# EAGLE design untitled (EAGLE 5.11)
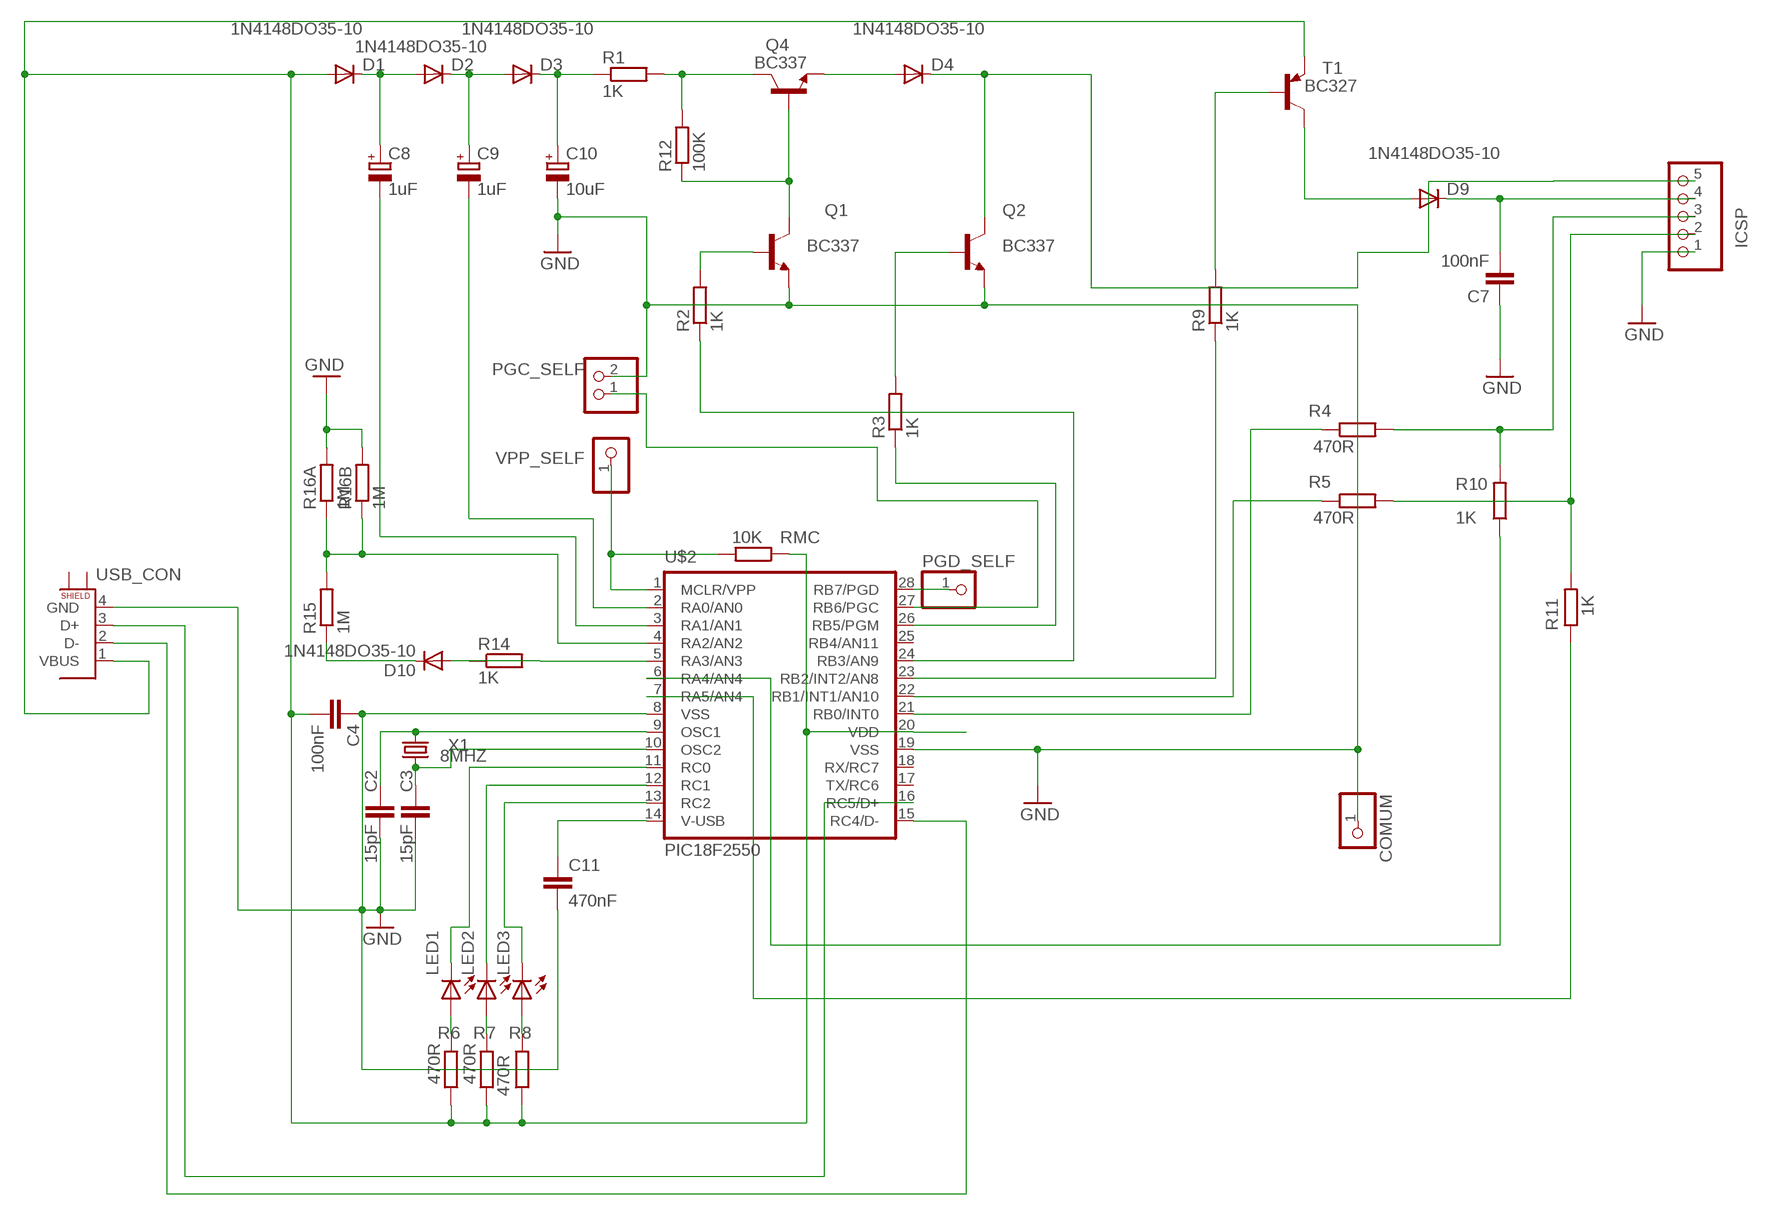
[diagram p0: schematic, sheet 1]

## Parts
C2  15pF  C-EU025-024X044  [C025-024X044]
C3  15pF  C-EU025-024X044  [C025-024X044]
C4  100nF  C-EU025-025X050  [C025-025X050]
C7  100nF  C-EU025-025X050  [C025-025X050]
C8  1uF  CPOL-EUE2-5  [E2-5]
C9  1uF  CPOL-EUE2-5  [E2-5]
C10  10uF  CPOL-EUE2-5  [E2-5]
C11  470nF  C-EU025-025X050  [C025-025X050]
COMUM  PINHD-1X1  [1X01]
D1  1N4148DO35-10  [DO35-10]
D2  1N4148DO35-10  [DO35-10]
D3  1N4148DO35-10  [DO35-10]
D4  1N4148DO35-10  [DO35-10]
D9  1N4148DO35-10  [DO35-10]
D10  1N4148DO35-10  [DO35-10]
ICSP  PINHD-1X5  [1X05]
LED1  LED3MM  [LED3MM]
LED2  LED3MM  [LED3MM]
LED3  LED3MM  [LED3MM]
PGC_SELF  PINHD-1X2  [1X02]
PGD_SELF  PINHD-1X1  [1X01]
Q1  BC337  [TO92]
Q2  BC337  [TO92]
Q4  BC337  [TO92]
R1  1K  R-EU_0207/10  [0207/10]
R2  1K  R-EU_0207/10  [0207/10]
R3  1K  R-EU_0207/10  [0207/10]
R4  470R  R-EU_0207/10  [0207/10]
R5  470R  R-EU_0207/10  [0207/10]
R6  470R  R-EU_0207/10  [0207/10]
R7  470R  R-EU_0207/10  [0207/10]
R8  470R  R-EU_0207/10  [0207/10]
R9  1K  R-EU_0207/10  [0207/10]
R10  1K  R-EU_0207/10  [0207/10]
R11  1K  R-EU_0207/10  [0207/10]
R12  100K  R-EU_0207/10  [0207/10]
R14  1K  R-EU_0207/10  [0207/10]
R15  1M  R-EU_0207/10  [0207/10]
R16A  1M  R-EU_0207/10  [0207/10]
R16B  1M  R-EU_0207/10  [0207/10]
RMC  10K  R-EU_0207/10  [0207/10]
T1  BC327  BC327-40-PNP-TO92-EBC  [TO92-EBC]
U$2  PIC18F2550  [DIL28-3]
USB_CON  USB-B  [PN61729]
VPP_SELF  PINHD-1X1  [1X01]
X1  8MHZ  CRYSTALHC49S  [HC49/S]

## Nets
GND: C2.2 C3.2 C4.1 C7.1 C10.- C11.2 COMUM.1 ICSP.1 PGC_SELF.2 Q1.1(E) Q2.1(E) R16A.2 R16B.2 U$2.8(VSS) U$2.19(VSS) USB_CON.4(GND)
N$1: C11.1 U$2.14(V-USB)
N$2: C8.+ D1.C D2.A
N$3: C9.+ D2.C D3.A
N$4: C10.+ D3.C R1.1
N$5: Q4.3(C) R1.2 R12.2
N$6: Q1.3(C) Q4.2(B) R12.1
N$7: Q1.2(B) R2.2
N$8: D4.A Q4.1(E)
N$9: Q2.2(B) R3.2
N$10: C2.1 U$2.9(OSC1) X1.2
N$11: C3.1 U$2.10(OSC2) X1.1
N$12: RMC.2 U$2.1(MCLR/VPP) VPP_SELF.1
N$13: LED1.A R6.2
N$14: LED2.A R7.2
N$15: LED3.A R8.2
N$16: D10.A R14.1
N$17: PGC_SELF.1 U$2.27(RB6/PGC)
N$18: R9.2 T1.B
N$19: C7.2 D9.C ICSP.4
N$20: ICSP.3 R4.2 R10.2
N$21: D9.A T1.C
N$22: ICSP.2 R5.2 R11.2
N$23: R15.2 R16A.1 R16B.1 U$2.4(RA2/AN2)
N$24: R3.1 U$2.26(RB5/PGM)
N$25: R14.2 U$2.5(RA3/AN3)
N$26: PGD_SELF.1 U$2.28(RB7/PGD)
PGC: R5.1 U$2.22(RB1/INT1/AN10)
PGD: R4.1 U$2.21(RB0/INT0)
PUMP1: C8.- U$2.3(RA1/AN1)
PUMP2: C9.- U$2.2(RA0/AN0)
RA4: R10.1 U$2.6(RA4/AN4)
RA5: R11.1 U$2.7(RA5/AN4)
RC0: LED1.K(C) U$2.11(RC0)
RC1: LED2.K(C) U$2.12(RC1)
RC2: LED3.K(C) U$2.13(RC2)
USBD+: U$2.16(RC5/D+) USB_CON.3(D+)
USBD-: U$2.15(RC4/D-) USB_CON.2(D-)
USBVDD: C4.2 D1.A R6.1 R7.1 R8.1 RMC.1 T1.E U$2.20(VDD) USB_CON.1(VBUS)
VDD_CTL: R9.1 U$2.23(RB2/INT2/AN8)
VPP: D4.C D10.C ICSP.5 Q2.3(C) R15.1
VPP_CTL: R2.1 U$2.24(RB3/AN9)
Unconnected: U$2.17(TX/RC6) U$2.18(RX/RC7) U$2.25(RB4/AN11) USB_CON.G1 USB_CON.G2

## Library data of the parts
C2-C4 C7 C11 = resistor:C-EU: CAPACITOR, European symbol
C8-C10 = resistor:CPOL-EU: POLARIZED CAPACITOR, European symbol
COMUM PGD_SELF VPP_SELF = pinhead:PINHD-1X1: PIN HEADER
D1-D4 D9 D10 = diode:1N4148: DIODE
ICSP = pinhead:PINHD-1X5: PIN HEADER
LED1-LED3 = led:LED: LED
PGC_SELF = pinhead:PINHD-1X2: PIN HEADER
Q1 Q2 Q4 = transistor:BC337: NPN TRANSISTOR
R1-R12 R14 R15 R16A R16B RMC = resistor:R-EU_: RESISTOR, European symbol
T1 = transistor:*-PNP-: PNP Transistror
U$2 = SparkFun:PIC18F2550
USB_CON = ads4:USB-B: USB Type-B Connector
X1 = crystal:CRYSTAL: CRYSTAL; OC_FARNELL: 1667008; OC_NEWARK: unknown

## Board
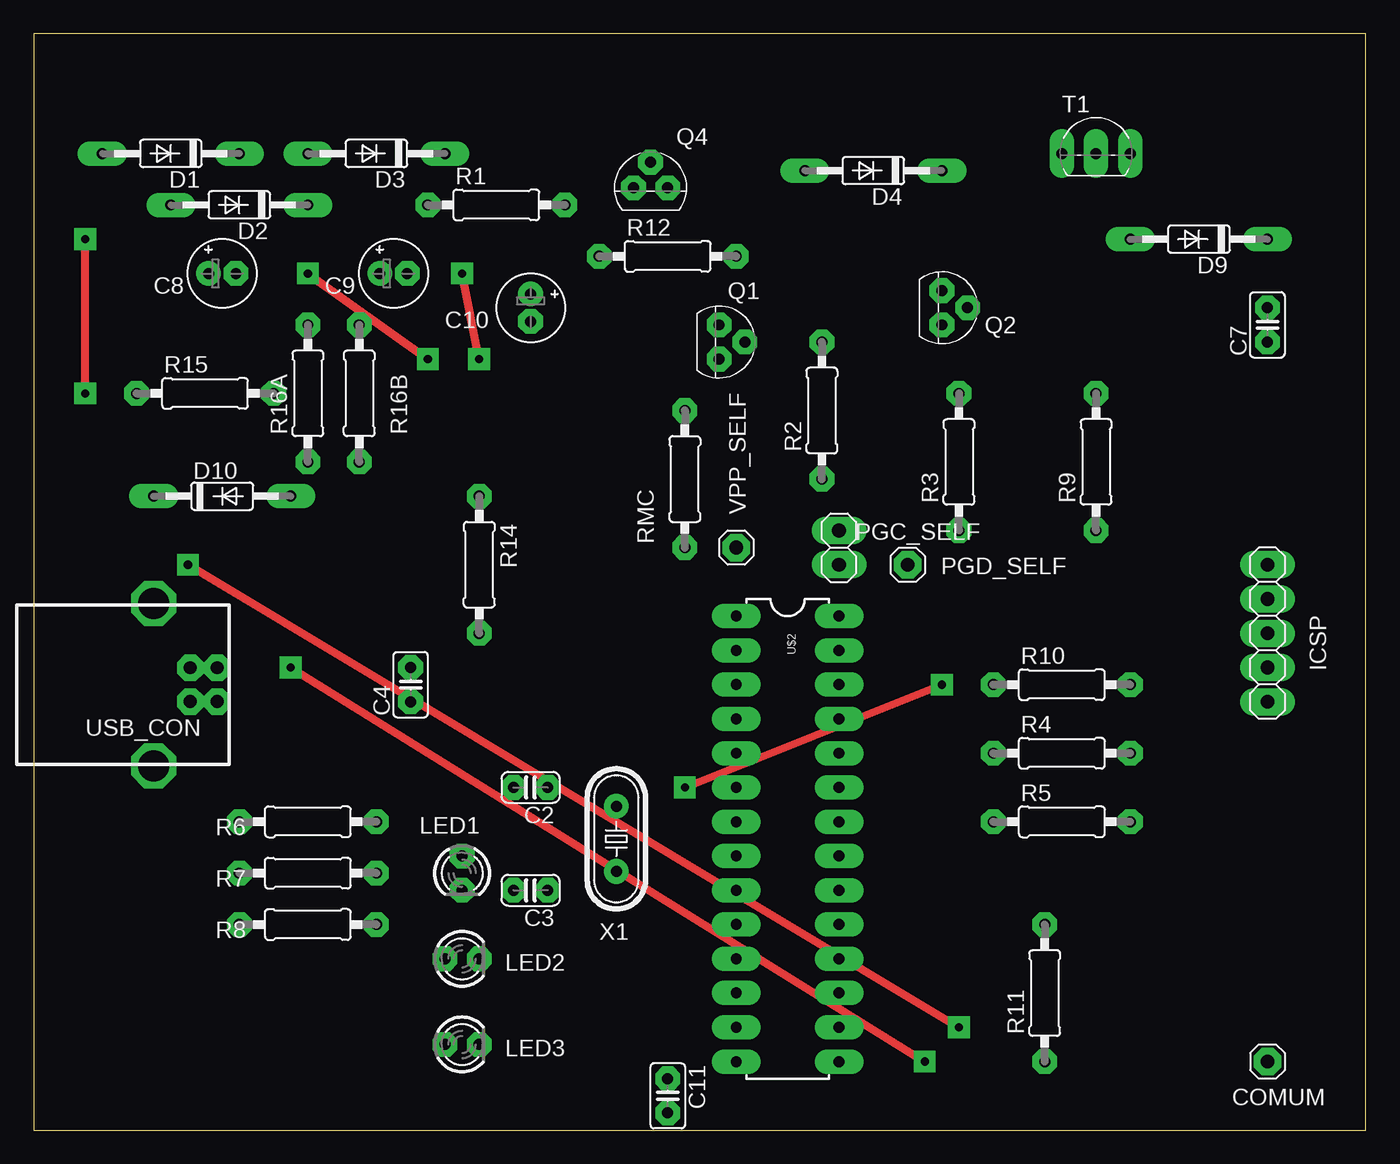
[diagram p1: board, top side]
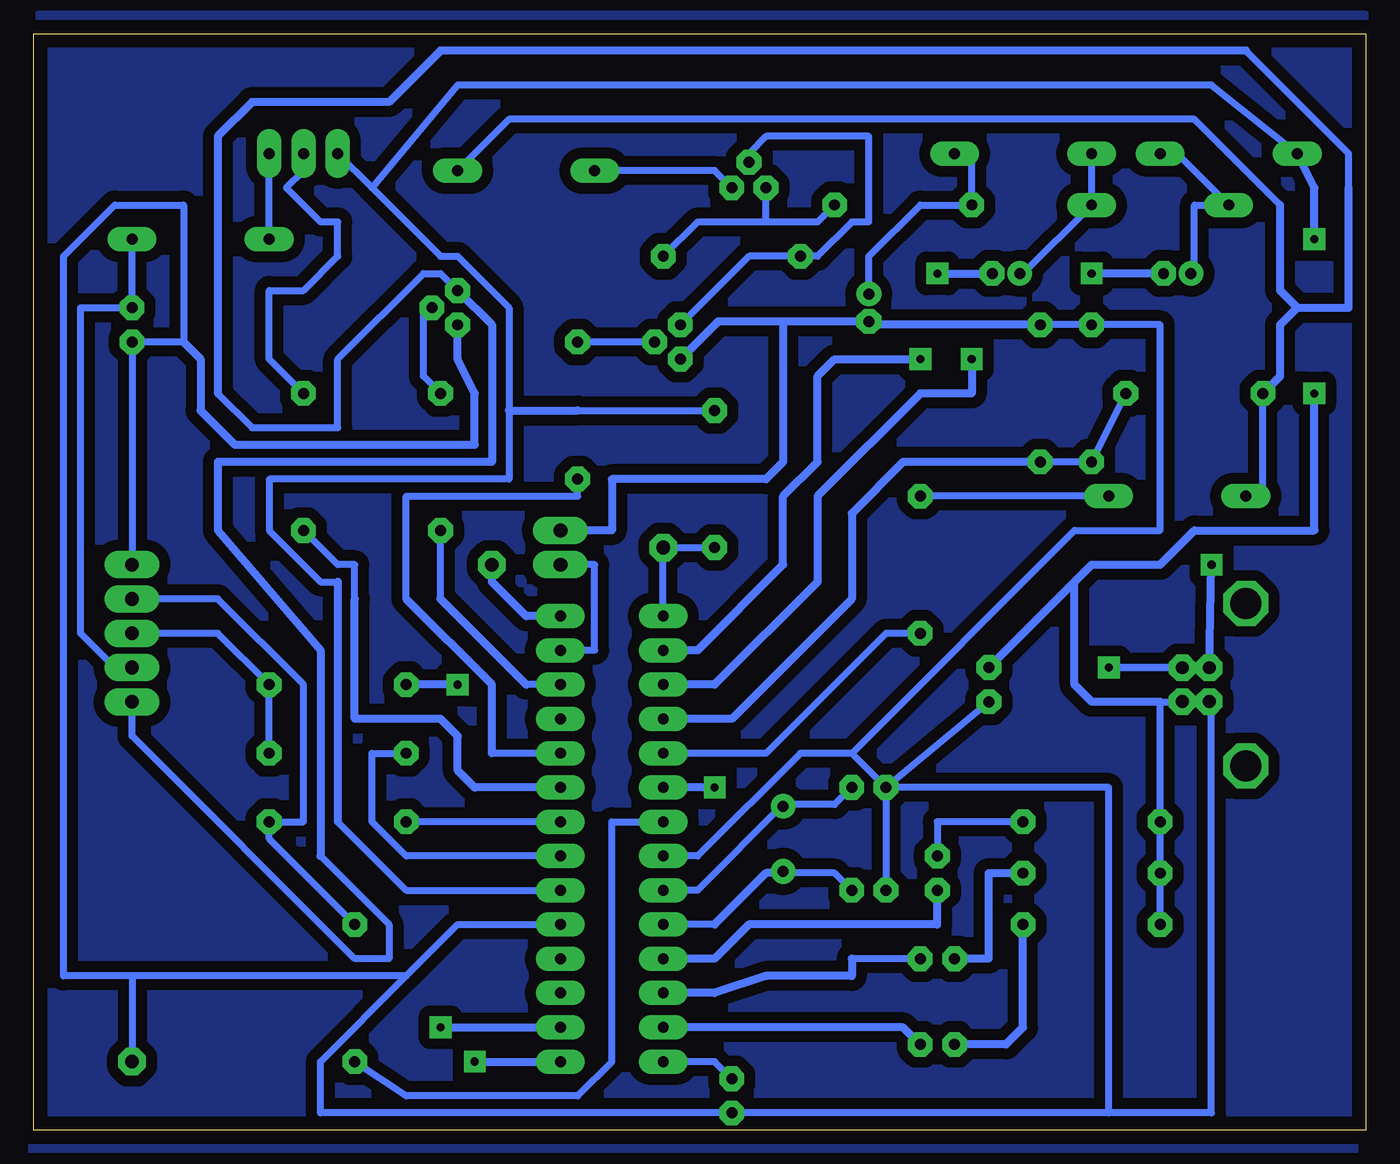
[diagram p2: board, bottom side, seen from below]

Size 98.73 x 81.27 mm. Coordinates in mm from the lower left corner, seen from the top.
Outline: 0,0 98.73,0 98.73,81.27 0,81.27 0,0
Copper layers (1*16): Top 0.035mm / dielectric 1.5mm / Bottom 0.035mm
Design rules "default *": minimum track width 20mil, minimum drill 24mil, track to track 20mil, track to pad 20mil, pad to pad 20mil, via to via 20mil, smd to smd 8mil, copper to edge 40mil, drill to drill 8mil, minimum pad ring 20mil, minimum via ring 20mil, stop-mask expansion 4mil, vias tented up to drill 0mil, thermal gap 10mil

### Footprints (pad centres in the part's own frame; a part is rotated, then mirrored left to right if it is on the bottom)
C025-024X044 = drill 0.813 octagon: 1 -1.27,0; 2 1.27,0
C025-025X050 = drill 0.813 octagon: 1 -1.27,0; 2 1.27,0
E2-5 = drill 0.813 pad 1.27 round: + -1.016,0 | drill 0.813 pad 1.27 octagon: - 1.016,0
1X01 = drill 1.016 octagon: 1 0,0
DO35-10 = drill 0.813 long: A 5.08,0; C -5.08,0
1X05 = drill 1.016 long: 1 -5.08,0; 2 -2.54,0; 3 0,0; 4 2.54,0; 5 5.08,0
LED3MM = drill 0.813 octagon: A -1.27,0; K 1.27,0
1X02 = drill 1.016 long: 1 -1.27,0; 2 1.27,0
TO92 = drill 0.813 octagon: 1 1.27,0; 2 0,1.905; 3 -1.27,0
0207/10 = drill 0.813 octagon: 1 -5.08,0; 2 5.08,0
TO92-EBC = drill 0.813 long: B 0,-1.27; C 2.54,-1.27; E -2.54,-1.27
DIL28-3 = drill 0.813 long: 1 -16.51,-3.81; 2 -13.97,-3.81; 3 -11.43,-3.81; 4 -8.89,-3.81; 5 -6.35,-3.81; 6 -3.81,-3.81; 7 -1.27,-3.81; 8 1.27,-3.81; 9 3.81,-3.81; 10 6.35,-3.81; 11 8.89,-3.81; 12 11.43,-3.81; 13 13.97,-3.81; 14 16.51,-3.81; 15 16.51,3.81; 16 13.97,3.81; 17 11.43,3.81; 18 8.89,3.81; 19 6.35,3.81; 20 3.81,3.81; 21 1.27,3.81; 22 -1.27,3.81; 23 -3.81,3.81; 24 -6.35,3.81; 25 -8.89,3.81; 26 -11.43,3.81; 27 -13.97,3.81; 28 -16.51,3.81
PN61729 = drill 0.95 octagon: 1 1.25,4.71; 2 -1.25,4.71; 3 -1.25,2.71; 4 1.25,2.71 | drill 2.3 octagon: G1 -6.02,0; G2 6.02,0
HC49/S = drill 0.813 round: 1 -2.413,0; 2 2.413,0

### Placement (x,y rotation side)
C2  36.83,25.4 180 top
C3  36.83,17.78 180 top
C4  27.94,33.02 90 top
C7  91.44,59.69 90 top
C8  13.97,63.5 0 top
C9  26.67,63.5 0 top
C10  36.83,60.96 270 top
C11  46.99,2.54 270 top
COMUM  91.44,5.08 0 top
D1  10.16,72.39 180 top
D2  15.24,68.58 180 top
D3  25.4,72.39 180 top
D4  62.23,71.12 180 top
D9  86.36,66.04 180 top
D10  13.97,46.99 0 top
ICSP  91.44,36.83 270 top
LED1  31.75,19.05 270 top
LED2  31.75,12.7 0 top
LED3  31.75,6.35 0 top
PGC_SELF  59.69,43.18 90 top
PGD_SELF  64.77,41.91 0 top
Q1  50.8,58.42 270 top
Q2  67.31,60.96 270 top
Q4  45.72,69.85 0 top
R1  34.29,68.58 0 top
R2  58.42,53.34 90 top
R3  68.58,49.53 90 top
R4  76.2,27.94 0 top
R5  76.2,22.86 0 top
R6  20.32,22.86 0 top
R7  20.32,19.05 0 top
R8  20.32,15.24 0 top
R9  78.74,49.53 90 top
R10  76.2,33.02 0 top
R11  74.93,10.16 90 top
R12  46.99,64.77 0 top
R14  33.02,41.91 270 top
R15  12.7,54.61 0 top
R16A  20.32,54.61 90 top
R16B  24.13,54.61 90 top
RMC  48.26,48.26 270 top
T1  78.74,73.66 0 top
U$2  55.88,21.59 270 top
USB_CON  8.89,33.02 270 top
VPP_SELF  52.07,43.18 0 top
X1  43.18,21.59 90 top

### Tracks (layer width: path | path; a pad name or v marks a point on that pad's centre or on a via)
GND
  Bottom 0.508: R16B.2 R16A.2 15.24,59.69 15.24,44.45 21.59,44.45 38.1,27.94 | C2.2 C4.1 | U$2.19 67.31,15.24 71.12,11.43 | 71.12,11.43 77.47,5.08 77.47,1.27 C11.2 19.05,1.27 | ICSP.1 C7.1 87.63,58.42 87.63,68.58 92.71,68.58 96.52,64.77 96.52,11.43 91.44,11.43 | 71.12,11.43 91.44,11.43 | U$2.8 49.53,20.32 41.91,27.94 38.1,27.94 | C2.2 38.1,27.94 | 19.05,1.27 11.43,1.27 11.43,31.75 USB_CON.4 | C2.2 C3.2 | C2.2 19.05,25.4 19.05,1.27 | 91.44,11.43 COMUM.1
  Bottom 0.61: Q2.1 67.31,57.15 66.04,54.61 66.04,50.8 83.82,50.8 86.36,53.34 86.36,57.15 87.63,58.42 | R16B.2 36.58,59.69 C10.- 43.18,59.94 | 43.18,59.94 48.01,59.94 Q1.1 | PGC_SELF.2 55.88,44.45 55.88,48.26 44.45,48.26 43.18,49.53 43.18,59.94
N$1
  Bottom 0.508: C11.1 48.26,5.08 U$2.14
N$2
  Bottom 0.508: D1.C 13.97,72.39 D2.A 12.7,68.58 12.7,63.5 C8.+
N$3
  Bottom 0.508: C9.+ 25.4,63.5 D2.C D3.A
N$4
  Bottom 0.508: D3.C 29.21,72.39 R1.1 33.02,68.58 36.83,64.77 C10.+
N$5
  Bottom 0.508: R1.2 40.64,67.31 44.45,67.31 | 44.45,67.31 49.53,67.31 R12.2 | 44.45,67.31 Q4.3
N$6
  Bottom 0.508: Q4.2 45.72,72.39 44.45,73.66 36.83,73.66 36.83,67.31 38.1,67.31 40.64,64.77 R12.1 45.72,64.77 Q1.3
N$7
  Bottom 0.508: Q1.2 R2.2
N$8
  Bottom 0.508: Q4.1 48.26,71.12 D4.A
N$9
  Bottom 0.508: R3.2 69.85,55.88 69.85,60.96 Q2.2
N$10
  Bottom 0.508: C2.1 39.37,24.13 43.18,24.13 | U$2.9 49.53,17.78 43.18,24.13 | 43.18,24.13 X1.2
N$11
  Bottom 0.508: C3.1 39.37,19.05 43.18,19.05 X1.1 | 48.26,15.24 U$2.10
  Bottom 0.61: 48.26,15.24 44.45,19.05 43.31,19.05 X1.1
N$12
  Bottom 0.508: U$2.1 VPP_SELF.1 RMC.2
N$13
  Bottom 0.508: LED1.A 31.75,22.86 R6.2
N$14
  Bottom 0.61: R7.2 27.94,19.05 27.94,12.7 LED2.A
N$15
  Bottom 0.61: LED3.A 26.67,6.35 25.4,7.62 R8.2
N$16
  Bottom 0.508: D10.A R14.1
N$17
  Bottom 0.508: U$2.27 57.15,35.56 57.15,41.91 PGC_SELF.1
N$18
  Bottom 0.508: R9.2 81.28,57.15 81.28,62.23 78.74,62.23 76.2,64.77 76.2,67.31 77.47,67.31 80.01,69.85 78.74,71.12 T1.B
N$19
  Bottom 0.508: D9.C C7.2 95.25,60.96 95.25,36.83 92.71,34.29 ICSP.4
N$20
  Bottom 0.508: R4.2 R10.2 85.09,36.83 ICSP.3
N$21
  Bottom 0.508: D9.A T1.C
N$22
  Bottom 0.508: R11.2 81.28,21.59 R5.2 78.74,22.86 78.74,33.02 85.09,39.37 ICSP.2
N$23
  Bottom 0.508: R15.2 R16A.1 R16B.1
  Bottom 0.61: R16B.1 34.29,49.53 38.1,45.72 38.1,39.37 46.99,30.48 U$2.4
N$24
  Bottom 0.508: U$2.26 62.23,33.02 | 68.58,39.37 R3.1
  Bottom 0.61: 62.23,33.02 68.58,39.37
N$25
  Bottom 0.508: U$2.5 44.45,27.94 35.56,36.83 R14.2
N$26
  Bottom 0.61: U$2.28 62.23,38.1 64.77,40.64 PGD_SELF.1
N$27
  pour Bottom (isolate 0.813): 0,0 0,82.55 98.42,82.55 99.06,81.92 99.06,-1.27 0.64,-1.27 0,-0.64
PGC
  Bottom 0.508: U$2.22 R5.1
PGD
  Bottom 0.508: U$2.21 71.12,20.32 73.66,22.86 73.66,27.94 R4.1
PUMP1  (via drill 0.6)
  Top 0.61: v20.32,63.5 v29.21,57.15
  Bottom 0.61: C8.- v20.32,63.5 | U$2.3 48.26,33.02 40.64,40.64 40.64,46.99 33.02,54.61 29.21,54.61 v29.21,57.15
PUMP2  (via drill 0.6)
  Top 0.61: v33.02,57.15 v31.75,63.5
  Bottom 0.61: v31.75,63.5 C9.- | v33.02,57.15 39.37,57.15 40.64,55.88 40.64,49.53 43.18,46.99 43.18,41.91 49.53,35.56 U$2.2
RA4  (via drill 0.6)
  Top 0.61: v48.26,25.4 v67.31,33.02
  Bottom 0.61: v67.31,33.02 R10.1 | v48.26,25.4 U$2.6
RA5
  Bottom 0.508: R11.1 71.12,2.54 58.42,2.54 55.88,5.08 55.88,22.86 U$2.7
RC0
  Bottom 0.61: U$2.11 48.26,12.7 45.72,15.24 31.75,15.24 LED1.K
RC1
  Bottom 0.508: LED2.K 38.1,12.7
  Bottom 0.61: 38.1,12.7 38.1,11.43 44.45,11.43 48.26,10.16 U$2.12
RC2
  Bottom 0.61: U$2.13 34.29,7.62 LED3.K
USBD+  (via drill 0.6)
  Top 0.61: v11.43,41.91 v68.58,7.62
  Bottom 0.61: v68.58,7.62 U$2.16 | USB_CON.3 v11.43,41.91
USBD-  (via drill 0.6)
  Top 0.61: v19.05,34.29 v66.04,5.08
  Bottom 0.61: USB_CON.2 v19.05,34.29 | v66.04,5.08 U$2.15
USBVDD  (via drill 0.6)
  Top 0.61: v3.81,54.61 v3.81,66.04
  Bottom 0.508: U$2.20 71.12,17.78 76.2,22.86 | 76.2,40.64 77.47,40.64 81.28,44.45 81.28,48.26 63.5,48.26 63.5,53.34 63.5,60.96 67.31,64.77 68.58,64.77 73.66,69.85 | 58.42,53.34 RMC.1 | D1.A 11.43,77.47 67.31,77.47 73.66,69.85 | R8.1 R7.1 R6.1 15.24,31.75 13.97,31.75 USB_CON.1 | 73.66,69.85 T1.E
  Bottom 0.61: 76.2,40.64 76.2,22.86 | v3.81,66.04 3.81,69.85 D1.A | v3.81,54.61 3.81,44.45 12.7,44.45 15.24,41.91 20.32,41.91 21.59,40.64 | 21.59,40.64 C4.2 | 15.24,31.75 20.32,31.75 21.59,33.02 21.59,40.64 | 63.5,53.34 58.42,53.34
VDD_CTL
  Bottom 0.508: R9.1 76.2,41.91 74.93,41.91 74.93,39.37
  Bottom 0.61: U$2.23 66.04,25.4 67.31,26.67 67.31,29.21 68.58,30.48 74.93,30.48 74.93,39.37
VPP
  Bottom 0.508: 77.47,20.32 72.39,15.24 72.39,12.7 74.93,12.7 91.44,29.21 ICSP.5 | D4.C 63.5,74.93 12.7,74.93 6.35,68.58 | D10.C 7.62,46.99 R15.1 | Q2.3 68.58,63.5 69.85,63.5 76.2,57.15 76.2,52.07 82.55,52.07 85.09,54.61 | 8.89,80.01 1.27,72.39 1.27,69.85
  Bottom 0.61: Q2.3 64.77,59.69 64.77,49.53 85.09,49.53 85.09,44.45 77.47,35.56 77.47,20.32 | 1.27,69.85 1.27,60.96 5.08,60.96 | 6.35,68.58 6.35,62.23 5.08,60.96 | 5.08,60.96 6.35,59.69 6.35,55.88 R15.1 | 8.89,80.01 68.58,80.01 72.39,76.2 82.55,76.2 85.09,73.66 85.09,54.61
VPP_CTL
  Bottom 0.508: R2.1 58.42,46.99 71.12,46.99 71.12,39.37 | U$2.24 64.77,27.94
  Bottom 0.61: 64.77,27.94 64.77,33.02 71.12,39.37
